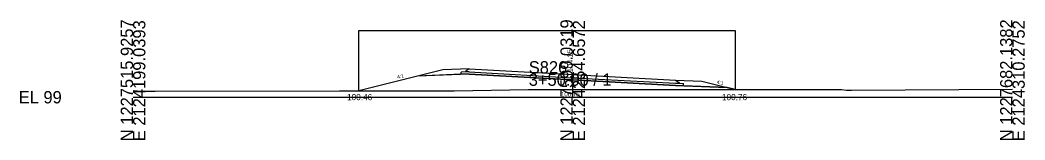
# Model space of a CAD drawing. Extents: x 2118382 to 2118616, y 1213030 to 1222057.
# Drawn here: x 2118381.9 to 2118610.4, y 1214030.1 to 1214057.3 of the extents above; entities that cross this region are included whole.
import ezdxf

# ---------------------------------------------------------------- set-up
doc = ezdxf.new("R2010")
doc.units = 0
for name, color, linetype in [('XS_CELL', 7, 'Continuous'), ('XS_M_DITCH', 7, 'Continuous'), ('XS_M_SHAPES_EARTHWORK', 7, 'Continuous'), ('XS_P_FINISHED_GRADE', 7, 'Continuous'), ('XS_P_FINISHED_GRADE_ELEV_TX', 7, 'Continuous'), ('XS_P_SUBGRADE_GRANULAR', 7, 'Continuous'), ('XS_P_SUBGRADE_PAVEMENT', 7, 'Continuous'), ('XS_P_TX_DCH', 7, 'Continuous'), ('XS_P_TX_FS_BS', 7, 'Continuous'), ('XS_X_GROUND', 7, 'Continuous'), ('XS_X_GROUND_TX', 7, 'Continuous')]:
    doc.layers.add(name, color=color, linetype=linetype)

msp = doc.modelspace()

# ---------------------------------------------------------------- linework, layer by layer
at = {"layer": 'XS_CELL'}
for p, q in [((2118507.6, 1214039.8), (2118507.6, 1214045.19)), ((2118407.6, 1214039.8), (2118507.6, 1214039.8)), ((2118507.6, 1214039.8), (2118607.6, 1214039.8))]:
    msp.add_line(p, q, dxfattribs=at)
at = {"layer": 'XS_M_DITCH'}
for p, q in [((2118458.97, 1214041.26), (2118458.97, 1214054.95)), ((2118458.97, 1214054.95), (2118544.58, 1214054.95)), ((2118544.58, 1214054.95), (2118544.58, 1214041.56))]:
    msp.add_line(p, q, dxfattribs=at)
at = {"layer": 'XS_M_SHAPES_EARTHWORK'}
for p, q in [((2118472.32, 1214044.6), (2118458.97, 1214041.26)), ((2118507.6, 1214043.74), (2118484.08, 1214045.07)), ((2118530.98, 1214042.49), (2118507.6, 1214043.74)), ((2118458.97, 1214041.26), (2118468.15, 1214041.26)), ((2118468.15, 1214041.26), (2118479.47, 1214041.25)), ((2118479.47, 1214041.25), (2118480.64, 1214041.26)), ((2118480.64, 1214041.26), (2118497.53, 1214041.55)), ((2118497.53, 1214041.55), (2118507.6, 1214041.55)), ((2118507.6, 1214041.55), (2118544.58, 1214041.56)), ((2118544.58, 1214041.56), (2118542.74, 1214042.02))]:
    msp.add_line(p, q, dxfattribs=at)
for points in [[(2118484.08, 1214045.07), (2118482.24, 1214045), (2118472.32, 1214044.6)], [(2118542.74, 1214042.02), (2118532.83, 1214042.42), (2118530.98, 1214042.49)]]:
    msp.add_lwpolyline(points, dxfattribs=at)
at = {"layer": 'XS_P_FINISHED_GRADE'}
for p, q in [((2118478.08, 1214046.04), (2118458.97, 1214041.26)), ((2118484.08, 1214046.28), (2118478.08, 1214046.04)), ((2118484.08, 1214046.28), (2118507.6, 1214044.95)), ((2118507.6, 1214044.95), (2118530.98, 1214043.7)), ((2118530.98, 1214043.7), (2118536.98, 1214043.46)), ((2118536.98, 1214043.46), (2118544.58, 1214041.56))]:
    msp.add_line(p, q, dxfattribs=at)
at = {"layer": 'XS_P_SUBGRADE_GRANULAR'}
for p, q in [((2118483.24, 1214045.54), (2118482.24, 1214045.5)), ((2118482.24, 1214045), (2118482.24, 1214045.5)), ((2118484.08, 1214045.07), (2118472.32, 1214044.6)), ((2118484.08, 1214045.07), (2118507.6, 1214043.74)), ((2118507.6, 1214043.74), (2118530.98, 1214042.49)), ((2118531.83, 1214042.96), (2118532.83, 1214042.92)), ((2118532.83, 1214042.42), (2118532.83, 1214042.92)), ((2118530.98, 1214042.49), (2118542.74, 1214042.02))]:
    msp.add_line(p, q, dxfattribs=at)
at = {"layer": 'XS_P_SUBGRADE_PAVEMENT'}
for p, q in [((2118483.39, 1214045.8), (2118483.24, 1214045.54)), ((2118484.08, 1214045.57), (2118483.24, 1214045.54)), ((2118484.08, 1214046.28), (2118483.39, 1214045.8)), ((2118484.08, 1214045.57), (2118507.6, 1214044.24)), ((2118507.6, 1214044.24), (2118530.98, 1214042.99)), ((2118530.98, 1214043.7), (2118531.68, 1214043.21)), ((2118530.98, 1214042.99), (2118531.83, 1214042.96)), ((2118531.68, 1214043.21), (2118531.83, 1214042.96))]:
    msp.add_line(p, q, dxfattribs=at)
at = {"layer": 'XS_X_GROUND'}
for p, q in [((2118407.6, 1214041.36), (2118409.65, 1214041.2)), ((2118409.65, 1214041.2), (2118409.95, 1214041.18)), ((2118409.95, 1214041.18), (2118412.66, 1214041.18)), ((2118412.66, 1214041.18), (2118454.54, 1214041.25)), ((2118454.54, 1214041.26), (2118455.59, 1214041.27)), ((2118455.59, 1214041.27), (2118468.15, 1214041.26)), ((2118468.15, 1214041.26), (2118479.47, 1214041.25)), ((2118479.47, 1214041.25), (2118480.64, 1214041.26)), ((2118480.64, 1214041.26), (2118497.53, 1214041.55)), ((2118497.53, 1214041.55), (2118507.6, 1214041.55)), ((2118507.6, 1214041.55), (2118566.17, 1214041.56)), ((2118566.17, 1214041.56), (2118568.72, 1214041.57)), ((2118568.72, 1214041.57), (2118569.85, 1214041.42)), ((2118569.85, 1214041.42), (2118571.01, 1214041.43)), ((2118571.01, 1214041.43), (2118607.6, 1214041.6))]:
    msp.add_line(p, q, dxfattribs=at)

# ---------------------------------------------------------------- texts
at = {"layer": 'XS_CELL'}
for s, p in [('N 1227515.9257', (2118407.6, 1214029.8)), ('E 2124199.0393', (2118410.4, 1214029.8)), ('N 1227599.0319', (2118507.6, 1214029.8)), ('E 2124254.6572', (2118510.4, 1214029.8)), ('N 1227682.1382', (2118607.6, 1214029.8)), ('E 2124310.2752', (2118610.4, 1214029.8))]:
    msp.add_text(s, height=2.8, rotation=90, dxfattribs=at).set_placement(p)
for s, p in [('S826', (2118497.6, 1214045.19)), ('3+50.00 / 1', (2118497.6, 1214042.39)), ('EL 99', (2118381.6, 1214038.4))]:
    msp.add_text(s, height=2.8, dxfattribs=at).set_placement(p)
at = {"layer": 'XS_P_FINISHED_GRADE_ELEV_TX'}
msp.add_text(' 104.15', height=1.25, rotation=90, dxfattribs=at).set_placement((2118507.6, 1214044.96))
at = {"layer": 'XS_P_TX_DCH'}
for s, p in [('100.46', (2118456.27, 1214039.13)), ('100.76', (2118541.54, 1214039.13))]:
    msp.add_text(s, height=1.4, dxfattribs=at).set_placement(p)
at = {"layer": 'XS_P_TX_FS_BS'}
for rotation, p in [(14.0362, (2118467.77, 1214043.99)), (345.9638, (2118540.3, 1214042.93))]:
    msp.add_text('4:1', height=0.8, rotation=rotation, dxfattribs=at).set_placement(p)
at = {"layer": 'XS_X_GROUND_TX'}
msp.add_text('100.75', height=1, dxfattribs=at).set_placement((2118504.93, 1214039.99))

doc.saveas('drawing.dxf')
